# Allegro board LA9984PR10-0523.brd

Outline 237.4 x 193.1 mm; copper layers: TOP, GND1, IN1, VCC, IN2, IN3, GND2, BOTTOM. Coordinates in mm from the lower left corner of the outline.
Outline path: 0,122.4 24.21,122.4 arc(27.29,124.08) 29.86,121.7 arc(30.21,121.13) 30.84,120.9 37,120.9 arc(37.71,121.19) 38,121.9 38,122.4 48,122.4 arc(64.27,126.17) 77.23,136.71 arc(77.58,137) 78.02,137.1 78.62,137.1 arc(79.08,137.21) 79.44,137.53 arc(81.38,140.63) 83.02,143.9 arc(83.09,144.51) 82.79,145.04 arc(82.5,145.54) 82.54,146.13 arc(84.38,152.65) 85,159.4 85,161.8 88.93,161.8 88.93,155.52 arc(89.37,154.46) 90.43,154.02 117.73,154.02 arc(118.79,154.46) 119.23,155.52 119.23,161.8 123.5,161.8 arc(124.21,162.09) 124.5,162.8 124.5,192.1 148.32,192.1 arc(149.03,192.39) 149.32,193.1 174.82,193.1 arc(175.11,192.39) 175.82,192.1 198.4,192.1 198.4,184.1 arc(198.69,183.39) 199.4,183.1 210.2,183.1 210.2,182.6 arc(210.49,181.89) 211.2,181.6 233.2,181.6 arc(233.91,181.89) 234.2,182.6 234.2,183.1 237.4,183.1 237.4,174.1 234.9,174.1 234.9,91.45 231.4,91.45 arc(230.69,91.16) 230.4,90.45 230.4,0 165.4,0 165.4,9.48 arc(165.11,10.19) 164.4,10.48 89.4,10.48 89.4,13.48 arc(89.11,14.19) 88.4,14.48 76.6,14.48 76.6,16.98 arc(76.45,17.33) 76.1,17.48 72.1,17.48 arc(71.75,17.33) 71.6,16.98 71.6,14.48 62.4,14.48 arc(61.69,14.19) 61.4,13.48 61.4,9.65 18.8,9.65 arc(18.09,9.36) 17.8,8.65 17.8,6.5 0,6.5 0,10.84 12.33,10.84 12.33,18.69 0,18.69 0,23.6 7.12,23.6 arc(7.62,24.1) 7.12,24.6 7.12,36.21 arc(7.62,36.71) 7.12,37.21 0,37.21 0,41.25 10.07,41.25 arc(10.57,41.75) 10.07,42.25 10.07,53.75 arc(10.57,54.25) 10.07,54.75 0,54.75 0,58.85 10.07,58.85 arc(10.57,59.35) 10.07,59.85 10.07,71.35 arc(10.57,71.85) 10.07,72.35 0,72.35 0,76.66 12.5,76.66 arc(13,77.16) 12.5,77.66 12.5,91.94 arc(13,92.44) 12.5,92.94 0,92.94 0,97.9 6.55,97.9 arc(7.05,98.4) 6.55,98.9 6.55,112.4 arc(7.05,112.9) 6.55,113.4 0,113.4 0,122.4

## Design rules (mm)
net group CLK_: nets CLK_CPU_ITP CLK_CPU_ITP#
net group CSI: nets CSIN CSIP
net group DIFFPAIR2: nets I2C1_SCL_TCH_PAD I2C1_SDA_TCH_PAD
net group DIFFPAIR3: nets CSCL CSDA
net group DIFFPAIR5: nets EC_SMB_CK2 EC_SMB_DA2
net group DIFFPAIR6: nets CPU_DPB_CTRLCLK_R CPU_DPB_CTRLDAT_R
net group DIFFPAIR11: nets EDP_N1 EDP_P1
net group DIFFPAIR12: nets CPU_EDP_AUX#_C CPU_EDP_AUX_C
net group EDID_CLK: nets EDID_CLK EDID_DATA
net group MIIC_SCL: nets MIIC_SCL MIIC_SDA
net group PCIE_PRX_LANTX_P3_C: nets PCIE_PRX_LANTX_N3_C PCIE_PRX_LANTX_P3_C
net group PECI-SINGLE: nets PECI_EC PECI_KB9012
net group SENSE: nets VCCSENSE VSSSENSE
net group SMB-15: nets SML1_SMBCLK SML1_SMBDATA
net group VCIN0_PH: nets ECAGND VCIN0_PH
net group WCKA0_0: nets WCKA0_0 WCKA0B_0
net group WCKA0_1: nets WCKA0_1 WCKA0B_1
net group WCKA1_0: nets WCKA1_0 WCKA1B_0
net group WCKA1_1: nets WCKA1_1 WCKA1B_1
net group WCKB0_0: nets WCKB0_0 WCKB0B_0
net group WCKB0_1: nets WCKB0_1 WCKB0B_1
net group WCKB1_0: nets WCKB1_0 WCKB1B_0
net group WCKB1_1: nets WCKB1_1 WCKB1B_1
net group 12: nets PCH_OPI_COMP PCH_PCIE_RCOMP SATA_IREF
net group ASYNC: nets DDR3_DRAMRST# DDR3_DRAMRST#_CPU H_PROCHOT# H_PROCHOT#_R H_VCCST_PWRGD_XDP XDP_OBS0_R XDP_OBS1_R
net group AUDIO: nets PCH_AZ_BITCLK PCH_AZ_CODEC_BITCLK PCH_AZ_CODEC_RST# PCH_AZ_CODEC_SDIN0 PCH_AZ_CODEC_SDOUT PCH_AZ_CODEC_SYNC PCH_AZ_RST# PCH_AZ_SDOUT PCH_AZ_SYNC
net group CLK: nets SUSCLK
net group CLK-SINGLE: nets CLK_PCI_LPC
net group CR_LOW: nets DSWODVREN INTRUDER# PCH_DPWROK PCH_INTVRMEN PCH_RSMRST#_R SYS_PWROK SYS_PWROK_R SYS_RESET#
net group DDRA-ADD: nets DDR_A_BS0 DDR_A_BS1 DDR_A_BS2 DDR_A_CAS# DDR_A_MA0 DDR_A_MA1 DDR_A_MA2 DDR_A_MA3 DDR_A_MA4 DDR_A_MA5 DDR_A_MA6 DDR_A_MA7 DDR_A_MA8 DDR_A_MA9 DDR_A_MA10 DDR_A_MA11 DDR_A_MA12 DDR_A_MA13 DDR_A_MA14 DDR_A_MA15 DDR_A_RAS# DDR_A_WE#
net group DDRA-CTL: nets DDR_CKE0_DIMMA DDR_CKE1_DIMMA DDR_CS0_DIMMA# DDR_CS1_DIMMA# M_ODT0 M_ODT1
net group DDRA-D0: nets DDR_A_D0 DDR_A_D1 DDR_A_D2 DDR_A_D3 DDR_A_D4 DDR_A_D5 DDR_A_D6 DDR_A_D7
net group DDRA-D1: nets DDR_A_D8 DDR_A_D9 DDR_A_D10 DDR_A_D11 DDR_A_D12 DDR_A_D13 DDR_A_D14 DDR_A_D15 DDR_A_DQS1 DDR_A_DQS#1
net group DDRA-D2: nets DDR_A_D16 DDR_A_D17 DDR_A_D18 DDR_A_D19 DDR_A_D20 DDR_A_D21 DDR_A_D22 DDR_A_D23
net group DDRA-D3: nets DDR_A_D24 DDR_A_D25 DDR_A_D26 DDR_A_D27 DDR_A_D28 DDR_A_D29 DDR_A_D30 DDR_A_D31
net group DDRA-D4: nets DDR_A_D32 DDR_A_D33 DDR_A_D34 DDR_A_D35 DDR_A_D36 DDR_A_D37 DDR_A_D38 DDR_A_D39
net group DDRA-D5: nets DDR_A_D40 DDR_A_D41 DDR_A_D42 DDR_A_D43 DDR_A_D44 DDR_A_D45 DDR_A_D46 DDR_A_D47
net group DDRA-D6: nets DDR_A_D48 DDR_A_D49 DDR_A_D50 DDR_A_D51 DDR_A_D52 DDR_A_D53 DDR_A_D54 DDR_A_D55
net group DDRA-D7: nets DDR_A_D56 DDR_A_D57 DDR_A_D58 DDR_A_D59 DDR_A_D60 DDR_A_D61 DDR_A_D62 DDR_A_D63
net group DDRB-ADD: nets DDR_B_BS0 DDR_B_BS1 DDR_B_BS2 DDR_B_CAS# DDR_B_MA0 DDR_B_MA1 DDR_B_MA2 DDR_B_MA3 DDR_B_MA4 DDR_B_MA5 DDR_B_MA6 DDR_B_MA7 DDR_B_MA8 DDR_B_MA9 DDR_B_MA10 DDR_B_MA11 DDR_B_MA12 DDR_B_MA13 DDR_B_MA14 DDR_B_MA15 DDR_B_RAS# DDR_B_WE#
net group DDRB-CTL: nets DDR_CKE2_DIMMB DDR_CKE3_DIMMB DDR_CS2_DIMMB# DDR_CS3_DIMMB# M_ODT2 M_ODT3
net group DDRB-D0: nets DDR_B_D0 DDR_B_D1 DDR_B_D2 DDR_B_D3 DDR_B_D4 DDR_B_D5 DDR_B_D6 DDR_B_D7
net group DDRB-D1: nets DDR_B_D8 DDR_B_D9 DDR_B_D10 DDR_B_D11 DDR_B_D12 DDR_B_D13 DDR_B_D14 DDR_B_D15
net group DDRB-D2: nets DDR_B_D16 DDR_B_D17 DDR_B_D18 DDR_B_D19 DDR_B_D20 DDR_B_D21 DDR_B_D22 DDR_B_D23
net group DDRB-D3: nets DDR_B_D24 DDR_B_D25 DDR_B_D26 DDR_B_D27 DDR_B_D28 DDR_B_D29 DDR_B_D30 DDR_B_D31
net group DDRB-D4: nets DDR_B_D32 DDR_B_D33 DDR_B_D34 DDR_B_D35 DDR_B_D36 DDR_B_D37 DDR_B_D38 DDR_B_D39
net group DDRB-D5: nets DDR_B_D40 DDR_B_D41 DDR_B_D42 DDR_B_D43 DDR_B_D44 DDR_B_D45 DDR_B_D46 DDR_B_D47
net group DDRB-D6: nets DDR_B_D48 DDR_B_D49 DDR_B_D50 DDR_B_D51 DDR_B_D52 DDR_B_D53 DDR_B_D54 DDR_B_D55
net group DDRB-D7: nets DDR_B_D56 DDR_B_D57 DDR_B_D58 DDR_B_D59 DDR_B_D60 DDR_B_D61 DDR_B_D62 DDR_B_D63
net group DP: nets CPU_DPB_AUX CPU_DPB_AUX# CPU_DPC_AUX CPU_DPC_AUX#
net group EDP: nets CPU_EDP_N0_C CPU_EDP_N1_C CPU_EDP_P0_C CPU_EDP_P1_C
net group HDA: nets AUD_HP_OUT_L_CN AUD_HP_OUT_R_CN HPOUT-L HPOUT-R MIC_IN MIC_IN_R RING2 RING2_R
net group HDMI: nets TMDS_L_TX0N TMDS_L_TX0P TMDS_L_TX1N TMDS_L_TX1P TMDS_L_TX2N TMDS_L_TX2P TMDS_L_TXCN TMDS_L_TXCP TMDS_TX0N TMDS_TX0P TMDS_TX1N TMDS_TX1P TMDS_TX2N TMDS_TX2P TMDS_TXCN TMDS_TXCP
net group KB: nets KSI0 KSI1 KSI2 KSI3 KSI4 KSI5 KSI6 KSI7 KSO0 KSO1 KSO2 KSO3 KSO4 KSO5 KSO6 KSO7 KSO8 KSO9 KSO10 KSO11 KSO12 KSO13 KSO14 KSO15 KSO16
net group LPC: nets LPC_LAD0 LPC_LAD1 LPC_LAD2 LPC_LAD3 LPC_LFRAME#
net group LVDS: nets EDP_AUX EDP_AUX# EDP_N0 EDP_P0 LVDS_A0+ LVDS_A0- LVDS_A1+ LVDS_A1- LVDS_A2+ LVDS_A2- LVDS_ACLK+ LVDS_ACLK- LVDS_B0+ LVDS_B0- LVDS_B1+ LVDS_B1- LVDS_B2+ LVDS_B2- LVDS_BCLK+ LVDS_BCLK-
net group PCIE: nets PCIE_PRX_LANTX_N3 PCIE_PRX_LANTX_P3 PCIE_PTX_LANRX_N3 PCIE_PTX_LANRX_P3 PCIE_PTX_WLANRX_N4_C PCIE_PTX_WLANRX_P4_C
net group PEG: nets PEG_CTX_GRX_N0 PEG_CTX_GRX_N1 PEG_CTX_GRX_N2 PEG_CTX_GRX_N3 PEG_CTX_GRX_P0 PEG_CTX_GRX_P1 PEG_CTX_GRX_P2 PEG_CTX_GRX_P3
net group POWER: nets +0.675VS +0.675VSP +1.05VS +1.5VS +1.5VSP +1.5VSP_ON +1.35V +1.35VP +1.35VS_VGA +3V_WLAN +3VALW_PCH +3VALWP +3VLP +3VS +3VS_CAM +3VS_RT +5V_HDD +5V_PVDD +5V_USB_PWR1 +5V_USB_PWR2 +5V_USB_PWR3 +5V_USB_PWR4 +5VA +5VALWP +5VS_ODD +AVCC33 +DIMM1_VREF_DQ +DIMM2_VREF_DQ +DVCC33 +EC_VCCA +FAN_POWER +INV_PWR_SRC +LAN_IO +LAN_VDD +LCDVDD +MIC2-VREFO +PCH_VCCDSW +PCH_VCCDSW_R +RTCBATT +RTCVCC +SM_VREF_CA +SM_VREF_CA_DIMM +SM_VREF_DQ0 +SM_VREF_DQ0_DIMM1 +SM_VREF_DQ1 +SM_VREF_DQ1_DIMM2 +SW_LX +SWR_V12 +V18R +VCC_3IN1 +VCC_PWR_SRC +VCCIO_OUT +VCCIOA_OUT +VCHGR +VDISPLAY_VCC +VGA_CORE
net group RCOMP: nets SM_RCOMP0 SM_RCOMP1 SM_RCOMP2
net group RTC: nets PCH_RTCRST# PCH_RTCX1 PCH_RTCX2 SRTCRST#
net group SATA: nets SATA_PRX_DTX_N0 SATA_PRX_DTX_N0_C SATA_PRX_DTX_N1 SATA_PRX_DTX_P0 SATA_PRX_DTX_P0_C SATA_PRX_DTX_P1 SATA_PTX_DRX_N0 SATA_PTX_DRX_N1 SATA_PTX_DRX_N1_C SATA_PTX_DRX_P0 SATA_PTX_DRX_P1 SATA_PTX_DRX_P1_C
net group SMB_10: nets DDR_XDP_SMBCLK_R1 DDR_XDP_SMBDAT_R1 SML0CLK SML0DATA
net group SPI: nets PCH_SPI_CLK PCH_SPI_CLK_R PCH_SPI_CS0# PCH_SPI_HOLD1# PCH_SPI_HOLD# PCH_SPI_MISO PCH_SPI_MISO_1 PCH_SPI_MOSI PCH_SPI_MOSI_1 PCH_SPI_WP1# PCH_SPI_WP#
net group SPK: nets INT-SPK-L+ INT-SPK-L- INT-SPK-R+ INT-SPK-R-
net group SVID: nets H_CPU_SVIDALRT# H_CPU_SVIDCLK H_CPU_SVIDDATA VR_SVID_ALRT# VR_SVID_CLK VR_SVID_DAT
net group THERMTRIP-SINGLE: nets H_THERMTRIP#
net group USB20: nets USB20_CAM_N7_R USB20_CAM_P7_R USB20_CR_N6_R USB20_CR_P6_R USB20_JUSB3_N2 USB20_JUSB3_N2_R USB20_JUSB3_P2 USB20_JUSB3_P2_R USB20_USBDB_N3_R USB20_USBDB_P3_R
net group USB30: nets USB3RN1_JUSB2 USB3RN1_JUSB2_R USB3RN2_JUSB1 USB3RN2_JUSB1_R USB3RP1_JUSB2 USB3RP1_JUSB2_R USB3RP2_JUSB1 USB3RP2_JUSB1_R USB3TN1_JUSB2_C USB3TN1_JUSB2_R USB3TN2_JUSB1_C USB3TN2_JUSB1_R USB3TP1_JUSB2_C USB3TP1_JUSB2_R USB3TP2_JUSB1_C USB3TP2_JUSB1_R
net group VRAMA1-D0: nets DDBIA1_0 DQA1_0 DQA1_1 DQA1_2 DQA1_3 DQA1_4 DQA1_5 DQA1_6 DQA1_7 EDCA1_0
net group VRAMA1-D1: nets DDBIA1_1 DQA1_8 DQA1_9 DQA1_10 DQA1_11 DQA1_12 DQA1_13 DQA1_14 DQA1_15 EDCA1_1
net group VRAMA1-D2: nets DDBIA1_2 DQA1_16 DQA1_17 DQA1_18 DQA1_19 DQA1_20 DQA1_21 DQA1_22 DQA1_23 EDCA1_2
net group VRAMA1-D3: nets DDBIA1_3 DQA1_24 DQA1_25 DQA1_26 DQA1_27 DQA1_28 DQA1_29 DQA1_30 DQA1_31 EDCA1_3
net group VRAMA-ADD: nets ADBIA0 ADBIA1 CASA0# CASA1# CKEA0 CKEA1 CSA0#_0 CSA1#_0 MAA0_0 MAA0_1 MAA0_2 MAA0_3 MAA0_4 MAA0_5 MAA0_6 MAA0_7 MAA0_8 MAA1_0 MAA1_1 MAA1_2 MAA1_3 MAA1_4 MAA1_5 MAA1_6 MAA1_7 MAA1_8 RASA0# RASA1# WEA0# WEA1#
net group VRAMA-D0: nets DDBIA0_0 DQA0_0 DQA0_1 DQA0_2 DQA0_3 DQA0_4 DQA0_5 DQA0_6 DQA0_7 EDCA0_0
net group VRAMA-D1: nets DDBIA0_1 DQA0_8 DQA0_9 DQA0_10 DQA0_11 DQA0_12 DQA0_13 DQA0_14 DQA0_15 EDCA0_1
net group VRAMA-D2: nets DDBIA0_2 DQA0_16 DQA0_17 DQA0_18 DQA0_19 DQA0_20 DQA0_21 DQA0_22 DQA0_23 EDCA0_2
net group VRAMA-D3: nets DDBIA0_3 DQA0_24 DQA0_25 DQA0_26 DQA0_27 DQA0_28 DQA0_29 DQA0_30 DQA0_31 EDCA0_3
net group VRAMB0-D0: nets DDBIB0_0 DQB0_0 DQB0_1 DQB0_2 DQB0_3 DQB0_4 DQB0_5 DQB0_6 DQB0_7 EDCB0_0
net group VRAMB0-D1: nets DDBIB0_1 DQB0_8 DQB0_9 DQB0_10 DQB0_11 DQB0_12 DQB0_13 DQB0_14 DQB0_15 EDCB0_1
net group VRAMB0-D2: nets DDBIB0_2 DQB0_16 DQB0_17 DQB0_18 DQB0_19 DQB0_20 DQB0_21 DQB0_22 DQB0_23 EDCB0_2
net group VRAMB0-D3: nets DDBIB0_3 DQB0_24 DQB0_25 DQB0_26 DQB0_27 DQB0_28 DQB0_29 DQB0_30 DQB0_31 EDCB0_3
net group VRAMB1-D0: nets DDBIB1_0 DQB1_0 DQB1_1 DQB1_2 DQB1_3 DQB1_4 DQB1_5 DQB1_6 DQB1_7 EDCB1_0
net group VRAMB1-D1: nets DDBIB1_1 DQB1_8 DQB1_9 DQB1_10 DQB1_11 DQB1_12 DQB1_13 DQB1_14 DQB1_15 EDCB1_1
net group VRAMB1-D2: nets DDBIB1_2 DQB1_16 DQB1_17 DQB1_18 DQB1_19 DQB1_20 DQB1_21 DQB1_22 DQB1_23 EDCB1_2
net group VRAMB1-D3: nets DDBIB1_3 DQB1_24 DQB1_25 DQB1_26 DQB1_27 DQB1_28 DQB1_29 DQB1_30 DQB1_31 EDCB1_3
net group VRAMB-ADD: nets ADBIB0 ADBIB1 CASB0# CASB1# CKEB0 CKEB1 CSB0#_0 CSB1#_0 DRAM_RST# DRAM_RST#_R MAB0_0 MAB0_1 MAB0_2 MAB0_3 MAB0_4 MAB0_5 MAB0_6 MAB0_7 MAB0_8 MAB1_0 MAB1_1 MAB1_2 MAB1_3 MAB1_4 MAB1_5 MAB1_6 MAB1_7 MAB1_8 RASB0# RASB1# WEB0# WEB1#
nets with their own width: min track width 0.254; nets +1.8VSP +3VALW +VGA_PCIEP CLK_BIASREF
nets with their own width: min track width 0.508; nets +1.2VSP_B+ +1.05V_PGOOD +1.05VS_APLLOPI +1.05VS_ASATA3PLL +1.05VS_AUSB3PLL +1.05VS_AXCK_DCB +1.05VS_AXCK_LCPLL +1.05VSP +1.8VGS +1.8VS +1.8VSP_ON +1.35V_MEM_GFX +1.35VGPUP +3VALW_PCH_GATE +3VGS +5VALW +5VS +AVDD +BIF_VDDC +CHGRTC +CPU_CORE +DPAB_VDD10 +DPAB_VDD18 +DPCD_VDD10 +DPCD_VDD18 +DPEF_VDD10 +DPEF_VDD18 +DPLL_PVDD +DPLL_VDDC +LCDVDD_CONN +MPV18 +PCIE_PVDD +PCIE_VDDR +SPV10 +SPV18 +TSVDD +VCCIO_OUT_R +VCCRTCEXT +VDD1DI +VDD_MEM15_REFDA +VDD_MEM15_REFDB +VDD_MEM15_REFSA +VDD_MEM15_REFSB +VDDC_CT +VDDCI +VDDCIP +VDDR4 +VREFG_GPU EDP_COMP GND GNDA

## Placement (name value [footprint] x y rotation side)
C35  -  [C_0402]  107.79 98.93 270 bottom
C36  -  [C_0402]  105.63 98.93 270 bottom
C37  -  [C_0402]  103.47 98.93 270 bottom
C38  -  [C_0402]  101.31 98.93 270 bottom
C39  -  [C_0603]  108.87 99.18 270 bottom
C40  -  [C_0603]  99.44 114.61 270 top
C41  -  [C_0603]  106.71 99.11 270 bottom
C42  -  [C_0603]  104.55 99.11 270 bottom
C43  -  [C_0603]  103.57 114.34 270 top
C44  -  [C_0603]  130.39 138.86 270 top
C45  -  [C_0603]  102.39 99.11 270 bottom
C50  -  [C_0402]  123.22 120.33 270 top
C51  -  [C_0402]  149.5 107.75 0 top
C52  -  [C_0402]  124.68 113.96 90 top
C53  -  [C_0402]  124.55 121.69 180 top
C54  -  [C_0402]  134.08 99.32 270 bottom
C55  -  [C_0402]  134.97 99.32 270 bottom
C56  -  [C_0402]  135.86 99.32 270 bottom
C57  -  [C_0402]  130.34 123.05 180 top
C58  -  [C_0402]  120.48 133.47 0 bottom
C59  -  [C_1206]  119.66 136.58 0 bottom
C60  -  [C_0603]  131.03 124.64 90 top
C61  -  [C_0402]  122.79 121.72 180 top
C62  -  [C_0402]  129.95 125.07 90 top
C63  -  [C_0402]  125.31 132.63 90 bottom
C64  -  [C_0402]  118.33 98.43 270 top
C65  -  [C_1206]  125.44 136.58 0 bottom
C66  -  [C_0603]  119.73 96.45 180 top
C67  -  [C_0402]  119.99 113.08 180 top
C68  -  [C_0402]  123.85 116.65 270 top
C69  -  [C_0402]  118.9 116.52 270 top
C70  -  [C_1206]  125.3 138.55 0 bottom
C71  -  [C_0402]  121.69 120.4 270 top
C72  -  [C_0603]  100.23 99.11 270 bottom
C73  -  [C_0402]  122.72 118.04 180 top
C74  -  [C_0603]  99.03 99.11 270 bottom
C75  -  [C_0402]  117.52 112.98 90 top
C76  -  [C_0402]  120.29 114.67 0 top
C77  -  [C_0402]  121.05 111.51 0 top
C78  -  [C_0603]  122.9 115.75 180 top
C79  -  [C_0402]  92.04 130.76 90 bottom
C80  -  [C_0402]  89.41 119.7 0 top
C81  -  [C_0402]  124.36 111.76 270 top
C82  -  [C_0603]  122.9 116.96 180 top
C83  -  [C_0402]  119.6 121.98 270 top
C84  -  [C_1206]  121.3 139.04 0 bottom
C85  -  [C_0402]  119.61 133.47 180 bottom
C86  -  [C_1206]  118.27 136.59 180 bottom
C87  -  [C_0402]  120.3 115.55 90 top
C88  -  [C_0402]  117.5 119.38 270 top
C2305  -  [C_0603]  190.4 21.58 180 top
C2306  -  [C_0603]  190.4 20.37 180 top
C2307  -  [C_0805]  199.46 20.7 0 top
C2308  -  [C_0603]  199.42 22.23 0 top
C2309  -  [C_0603]  187.97 19.94 180 top
C2310  -  [C_0805]  142.31 29.52 0 top
C2311  -  [C_0603]  142.9 24.13 0 top
C2312  -  [C_0603]  142.21 31.04 0 top
C2313  -  [C_0603]  142.9 22.93 0 top
C2314  -  [C_0603]  141.06 27.56 0 bottom
C2316  -  [C_0603]  190.97 17.9 180 top
C2318  -  [C_0603]  190.97 19.1 180 top
C2322  -  [C_0603]  187.97 18.74 180 top
C2323  -  [C_0603]  199.36 17.91 0 top
C2324  -  [C_0603]  199.36 19.12 0 top
C2326  -  [C_0402]  142.55 116.98 180 bottom
C2327  -  [C_0402]  168.06 92.91 180 bottom
C5212  -  [C_0402]  83.2 119.81 0 bottom
CA1  -  [C_0603]  27.4 25.97 0 bottom
CA2  -  [C_0603]  27.97 27.36 90 bottom
CA21  -  [C_0402]  46.69 24.37 0 top
CA22  -  [C_0402]  46.69 23.42 0 top
CA23  -  [C_0603]  32.48 26.28 0 top
CA24  -  [C_0402]  34.71 22.15 180 top
CA25  -  [C_0402]  33.35 23.17 0 top
CA29  -  [C_0402]  63.59 36.81 90 top
CA30  -  [C_0402]  63.59 35.94 270 top
CA31  -  [C_0402]  64.54 33.76 90 top
CA32  -  [C_0402]  64.54 32.89 270 top
CA33  -  [C_0402]  28.25 20.51 180 top
CA38  -  [C_0402]  19.64 25.33 90 top
CA39  -  [C_0402]  29.18 20.51 0 top
CA40  -  [C_0402]  19.64 24.46 270 top
CA51  -  [C_0402]  34.26 28.49 90 top
CA53  -  [C_0603]  42.45 18.35 270 top
CA54  -  [C_0402]  42.64 19.29 90 top
CA55  -  [C_0603]  43.59 18.15 0 top
CA56  -  [C_0402]  43.51 19.23 0 top
CA57  -  [C_0603]  44.35 21.07 0 top
CA58  -  [C_0402]  44.34 22.15 0 top
CA59  -  [C_0603]  44.48 27.61 0 top
CA60  -  [C_0402]  44.4 26.53 0 top
CA61  -  [C_0603]  37.18 17.15 180 top
CA62  -  [C_0603]  32.48 27.48 0 top
CA63  -  [C_0603]  35.78 18.53 90 top
CA64  -  [C_0603]  48.03 25.45 180 top
CA65  -  [C_0402]  44.4 28.69 0 top
CA67  -  [C_0603]  36.99 29.77 90 top
CA68  -  [C_0603]  38.19 29.77 90 top
CA69  -  [C_0402]  45.32 29.58 180 top
CA71  -  [C_0603]  33.18 28.56 90 top
CA74  -  [C_0603]  39.65 30.02 90 top
CC1  -  [C_0402]  146 101.14 0 bottom
CC2  -  [C_0402]  148.7 101.14 180 bottom
CC3  -  [C_0402]  129.45 96.77 90 top
CC4  -  [C_0402]  132.56 96.77 90 top
CC5  -  [C_0402]  127.21 97.27 0 bottom
CC6  -  [C_0402]  118.92 136.47 180 top
CC7  -  [C_0402]  114.45 136.47 0 top
CC8  -  [C_0402]  97.05 97.54 0 bottom
CC9  -  [C_0402]  94.41 97.54 180 bottom
CC10  -  [C_0402]  96.19 97.54 180 bottom
CC11  -  [C_0402]  149.5 105.4 0 top
CC13  -  [C_0402]  70.27 110.35 90 bottom
CC14  -  [C_0402]  62.7 103.69 90 bottom
CC15  -  [C_0402]  62.65 92.71 180 top
CC16  -  [C_0402]  61.89 90.7 270 bottom
CC17  -  [C_0402]  60.94 103.69 90 bottom
CC18  -  [C_0402]  158.88 119.95 0 bottom
CC19  -  [C_0402]  158.88 119.06 0 bottom
CC20  -  [C_0402]  160.66 121.47 0 bottom
CC21  -  [C_0402]  160.66 120.58 0 bottom
CC22  -  [C_0402]  158.88 122.74 0 bottom
CC23  -  [C_0402]  158.88 121.85 0 bottom
CC24  -  [C_0402]  160.66 124.52 0 bottom
CC25  -  [C_0402]  160.66 123.63 0 bottom
CC26  -  [C_0603]  136.93 99.3 270 bottom
CC27  -  [C_0402]  86.53 130.86 0 bottom
CC28  -  [C_0402]  78.98 124.51 90 bottom
CC29  -  [C_0402]  67.61 108.59 180 bottom
CC30  -  [C_0402]  62.2 106.95 270 bottom
CC31  -  [C_0402]  133.51 112.26 90 top
CC32  -  [C_0402]  39.91 102.02 90 bottom
CC33  -  [C_0402]  147.03 109.81 270 top
CC34  -  [C_0402]  135.3 113.73 180 top
CC35  -  [C_0402]  122.19 96.97 0 bottom
CC40  -  [C_0402]  39.02 102.02 90 bottom
CD1  -  [C_0402]  42.37 74.86 0 top
CD2  -  [C_0402]  42.37 75.74 0 top
CD3  -  [C_0402]  51.27 64.56 90 top
CD4  -  [C_0402]  73.88 64.49 90 top
CD5  -  [C_0402]  68.99 65.06 90 top
CD6  -  [C_0402]  66.7 65.41 270 top
CD7  -  [C_0402]  65.37 74.02 90 top
CD8  -  [C_0402]  69.94 72.68 90 top
CD9  -  [C_0402]  77.5 64.49 90 top
CD10  -  [C_0402]  77.18 72.68 90 top
CD11  -  [C_0402]  73.63 72.68 90 top
CD12  -  [C_0603]  75.72 64.57 90 top
CD13  -  [C_0603]  75.47 72.7 90 top
CD14  -  [C_0603]  78.96 72.7 90 top
CD15  -  [C_D3]  73.27 78.03 180 top
CD16  -  [C_0603]  67.91 64.57 90 top
CD17  -  [C_0603]  72.1 64.57 90 top
CD18  -  [C_0603]  79.34 64.57 90 top
CD19  -  [C_0603]  66.51 73.78 90 top
CD20  -  [C_0603]  71.78 72.7 90 top
CD21  -  [C_0402]  81.69 64.56 90 top
CD22  -  [C_0402]  82.58 64.56 90 top
CD23  -  [C_0402]  79.09 59.2 270 top
CD24  -  [C_0402]  105.26 72.76 180 top
CD25  -  [C_0402]  105.26 73.65 180 top
CD26  -  [C_0402]  105.01 64.95 180 top
CD27  -  [C_0402]  104.94 65.84 180 top
CD28  -  [C_0603]  105.29 66.92 180 top
CD29  -  [C_0603]  105.25 74.73 180 top
CD30  -  [C_0402]  102.57 72.75 90 top
CD31  -  [C_0402]  103.47 72.75 90 top
CD32  -  [C_0402]  120.41 75.43 0 top
CD33  -  [C_0402]  120.41 74.54 0 top
CD34  -  [C_0402]  129.31 64.56 90 top
CD35  -  [C_0402]  152.49 64.56 90 top
CD36  -  [C_0402]  148.87 64.56 90 top
CD37  -  [C_0402]  145.25 64.56 90 top
CD38  -  [C_0402]  156.05 64.49 90 top
CD39  -  [C_0402]  156.3 73.4 90 top
CD40  -  [C_0402]  153.51 73.4 90 top
CD41  -  [C_0402]  149.57 73.4 90 top
CD42  -  [C_0402]  144.62 73.4 90 top
CD43  -  [C_0603]  150.65 64.57 90 top
CD44  -  [C_0603]  147.03 64.57 90 top
CD45  -  [C_0603]  154.27 64.57 90 top
CD46  -  [C_0603]  146.14 73.47 90 top
CD47  -  [C_0603]  148.49 73.47 90 top
CD48  -  [C_0603]  151.98 73.47 90 top
CD49  -  [C_0603]  155.22 73.47 90 top
CD50  -  [C_0603]  157.89 64.57 90 top
CD51  -  [C_D3]  153.23 83.75 0 top
CD52  -  [C_0402]  160.3 64.56 90 top
CD53  -  [C_0402]  161.19 64.56 90 top
CD54  -  [C_0402]  183.62 74.28 180 top
CD55  -  [C_0402]  183.62 75.17 180 top
CD56  -  [C_0402]  183.56 64.57 180 top
CD57  -  [C_0402]  183.56 65.46 180 top
CD58  -  [C_0603]  183.83 66.54 180 top
CD59  -  [C_0603]  183.54 76.25 180 top
CD60  -  [C_0402]  180.94 74.27 90 top
CD61  -  [C_0402]  181.83 74.27 90 top
CD62  -  [C_0603]  101.44 72.74 90 top
CD63  -  [C_0402]  55.96 18.82 0 top
CD64  -  [C_0402]  83.86 59.31 180 top
CE1  -  [C_0402]  199.41 38.91 0 top
CE2  -  [C_0402]  191.54 35.75 270 top
CE5  -  [C_0402]  178.51 39.55 0 top
CE6  -  [C_0402]  185.49 34.94 90 top
CE7  -  [C_0402]  200.61 36.5 0 top
CE8  -  [C_0402]  196.31 55.79 90 top
CE9  -  [C_0402]  200.45 51.36 180 top
CE11  -  [C_0402]  199.47 41.84 0 top
CE12  -  [C_0402]  187.4 33.83 0 top
CE15  -  [C_0402]  178.08 57.32 90 top
CE16  -  [C_0805]  179.3 40.83 180 top
CE18  -  [C_0402]  178.58 46.85 0 top
CE19  -  [C_0402]  179.48 57.32 90 top
CE20  -  [C_0402]  195.55 32.81 90 top
CE22  -  [C_0603]  48.73 108.07 180 bottom
CE23  -  [C_0402]  48.81 106.99 180 bottom
CE24  -  [C_0402]  50.05 108.13 0 bottom
CE25  -  [C_0603]  44.73 104.32 270 bottom
CE26  -  [C_0402]  183.61 55.35 90 top
CE27  -  [C_0402]  184.62 35.85 270 top
CE28  -  [C_0402]  189.18 33.91 0 top
CE29  -  [C_0402]  193.96 35.75 270 top
CE30  -  [C_0402]  178.39 45.53 180 top
CE31  -  [C_0402]  196.83 35.82 270 top
CE32  -  [C_0402]  188.27 57.06 90 top
CE33  -  [C_0402]  181.19 34.99 0 top
CE34  -  [C_0402]  175.47 42.45 90 top
CE35  -  [C_0402]  174.41 40.74 0 top
CE36  -  [C_0402]  188.31 35.62 270 top
CE56  -  [C_0603]  42.95 104.65 0 top
CE57  -  [C_0603]  38.45 111.89 90 top
CE58  -  [C_0603]  33.61 98.38 0 top
CG1  -  [C_0402]  64.18 48.48 90 top
CG2  -  [C_0402]  63.41 42.36 270 top
CG3  -  [C_0402]  66.73 45.46 0 top
CG4  -  [C_0402]  60.35 46.92 180 top
CG5  -  [C_0805]  65.9 48.59 90 top
CG6  -  [C_0603]  62.14 48.52 90 top
CG7  -  [C_0402]  66.15 41.61 90 top
CG8  -  [C_0402]  60.29 42.47 0 top
CG9  -  [C_0402]  60.46 43.5 90 top
CG10  -  [C_0402]  62.53 42.36 270 top
CG11  -  [C_0402]  63.26 50.31 90 top
CI1  -  [C_MP6VLPS220MC4R2]  26.25 66.99 270 bottom
CI2  -  [C_0402]  19.21 65.98 270 bottom
CI3  -  [C_0402]  23.33 62.42 270 bottom
CI4  -  [C_0402]  24.22 62.42 270 bottom
CI6  -  [C_0805]  28.21 48.67 270 top
CI7  -  [C_0402]  29.54 47.77 270 top
CI8  -  [C_MP6VLPS220MC4R2]  26.25 52.83 270 bottom
CI9  -  [C_0402]  18.44 55.22 90 bottom
CI10  -  [C_0402]  23.7 49.89 0 bottom
CI11  -  [C_0402]  23.7 50.79 0 bottom
CI12  -  [C_0805]  28.83 61.6 0 top
CI13  -  [C_0402]  30.69 65.71 90 top
CI14  -  [C_0402]  29.61 64.65 0 top
CI15  -  [C_0402]  30.62 71.01 270 top
CI16  -  [C_0402]  21 36.2 180 top
CI17  -  [C_0402]  30.69 55.26 270 top
CI18  -  [C_0805]  28.83 59.88 0 top
CI19  -  [C_0402]  15.4 34.52 90 bottom
CI20  -  [C_MP6VLPS220MC4R2]  26.19 34.86 270 bottom
CI21  -  [C_0805]  28.83 63.31 0 top
CI22  -  [C_0402]  23 32.2 0 top
CI23  -  [C_0805]  22.04 33.53 0 top
CI24  -  [C_0402]  16.36 36.18 180 top
CI25  -  [C_0402]  213.4 37.53 180 bottom
CI26  -  [C_0402]  30.43 47.77 270 top
CI27  -  [C_0805]  22.7 35.03 90 top
CI30  -  [C_0402]  217.58 39.44 0 bottom
CI31  -  [C_0805]  216.81 40.77 0 bottom
CI32  -  [C_0402]  209.57 37.59 0 bottom
CI40  -  [C_0603]  20.29 66.54 270 bottom
CI43  -  [C_0603]  17.36 55.11 90 bottom
CI44  -  [C_0603]  14.32 34.34 90 bottom
CL15  -  [C_0402]  34.19 83.9 270 bottom
CL19  -  [C_0402]  42.95 86.11 270 bottom
CL20  -  [C_0402]  35.97 83.95 270 bottom
CL22  -  [C_0402]  34.2 91.3 180 bottom
CL26  -  [C_0402]  34.2 92.19 180 bottom
CL30  -  [C_0402]  42.07 91.82 270 bottom
CL31  -  [C_0402]  42.95 91.82 270 bottom
CL33  -  [C_1206]  19.21 81.78 270 top
CL34  -  [C_0402]  35.97 91.86 90 bottom
CL35  -  [C_0402]  35.08 91.86 90 bottom
CL36  -  [C_0402]  37.1 84.03 270 bottom
CL37  -  [C_0402]  38.57 83.1 90 bottom
CL38  -  [C_0603]  47.32 88.83 0 bottom
CL39  -  [C_0402]  43.78 84.13 180 bottom
CL41  -  [C_0402]  32.99 87.45 270 bottom
CM40  -  [C_0402]  93.31 148.19 0 top
CM43  -  [C_0603]  111.68 150.32 0 top
CM44  -  [C_0402]  108.33 149.73 90 top
CM45  -  [C_0603]  94.24 146.74 270 top
CM46  -  [C_0402]  115.87 149.7 90 top
CM47  -  [C_0402]  104.69 149.76 90 top
CM48  -  [C_0402]  110.73 149.74 90 top
CM49  -  [C_0402]  107.45 149.73 90 top
CMOS1  -  [SHORTPADS]  113.11 40.96 0 bottom
CR1  -  [C_0402]  177.96 20.77 270 top
CR2  -  [C_0603]  179.04 20.69 270 top
CR3  -  [C_0402]  180.11 19.85 90 top
CR4  -  [C_0402]  173.38 22.65 90 top
CR5  -  [C_0402]  181.78 22.85 180 top
CR6  -  [C_0402]  177.32 29.66 270 top
CR7  -  [C_0402]  182.26 30.6 0 top
CR8  -  [C_0603]  189.2 31.02 270 top
CR9  -  [C_0402]  179.49 28.78 0 top
CR10  -  [C_0402]  182.82 23.95 270 top
CR11  -  [C_0402]  175.16 28.74 90 top
CS5  -  [C_0402]  224.01 55.34 90 top
CS6  -  [C_0402]  223.12 55.34 90 top
CS7  -  [C_0805]  221.77 54.65 90 top
CS8  -  [C_0402]  224.7 103.89 180 bottom
CS9  -  [C_0402]  224.73 103.01 180 bottom
CS10  -  [C_0402]  223.18 115.5 180 bottom
CS11  -  [C_0402]  223.18 114.61 180 bottom
CS12  -  [C_0805]  223 113.21 180 bottom
CS13  -  [C_0402]  219.5 120.19 180 bottom
CS14  -  [C_0402]  224.77 109.16 180 bottom
CS15  -  [C_0402]  224.77 108.27 180 bottom
CS16  -  [C_0603]  223.07 124.75 0 bottom
CS17  -  [C_0402]  224.68 110.25 180 bottom
CS105  -  [C_0402]  224.39 30.02 180 top
CS106  -  [C_0402]  224.39 30.91 180 top
CS108  -  [C_0402]  224.39 32.69 180 top
CS109  -  [C_0402]  224.39 31.8 180 top
CV1  -  [C_0603]  196.62 158.55 90 top
CV3  -  [C_0603]  195.42 158.55 90 top
CV4  -  [C_0603]  218.53 124.39 0 top
CV5  -  [C_0603]  218.53 125.59 0 top
CV6  -  [C_0603]  218.02 104.13 270 top
CV7  -  [C_0603]  216.82 104.13 270 top
CV8  -  [C_0402]  164.43 158.22 90 top
CV9  -  [C_0402]  163.54 158.22 90 top
CV10  -  [C_0402]  194.85 158.15 90 bottom
CV11  -  [C_0402]  193.13 158.34 90 top
CV12  -  [C_0402]  219.03 133.97 0 top
CV13  -  [C_0402]  218.52 143.31 0 bottom
CV14  -  [C_0402]  165.89 158.22 90 bottom
CV15  -  [C_0402]  164.81 158.22 90 bottom
CV16  -  [C_0402]  163.92 158.22 90 bottom
CV17  -  [C_0402]  173.7 158.54 90 bottom
CV18  -  [C_0402]  219.48 145.1 270 bottom
CV19  -  [C_0402]  218.46 129.34 0 bottom
CV20  -  [C_0402]  218.46 127.56 0 bottom
CV21  -  [C_0402]  200.5 133.02 0 bottom
CV22  -  [C_0402]  201.41 134.8 180 bottom
CV23  -  [C_0402]  218.71 127.56 0 top
CV24  -  [C_0402]  219.62 129.34 180 top
CV25  -  [C_0402]  205.51 144.63 90 top
CV26  -  [C_0402]  203.74 145.54 270 top
CV27  -  [C_0402]  201.46 132.98 180 top
CV28  -  [C_0402]  200.55 130.35 0 top
CV29  -  [C_0402]  212.64 103.18 180 bottom
CV30  -  [C_0402]  211.73 101.4 0 bottom
CV31  -  [C_0402]  205.26 103.82 270 bottom
CV32  -  [C_0402]  203.48 102.91 90 bottom
CV33  -  [C_0402]  201.22 114.78 180 top
CV34  -  [C_0402]  200.31 116.56 0 top
CV35  -  [C_0402]  213.64 102.11 270 top
CV36  -  [C_0402]  211.86 101.19 90 top
CV37  -  [C_0402]  218.46 121.21 0 top
CV38  -  [C_0402]  218.46 119.43 0 top
CV39  -  [C_0402]  201.22 114.78 180 bottom
CV40  -  [C_0402]  200.31 116.56 0 bottom
CV41  -  [C_0603]  167.03 158.24 90 bottom
CV42  -  [C_0603]  162.78 158.17 90 bottom
CV43  -  [C_0402]  159.08 119.62 0 top
CV44  -  [C_0402]  159.08 118.73 0 top
CV45  -  [C_0402]  160.92 120.77 0 top
CV46  -  [C_0402]  160.92 119.88 0 top
CV47  -  [C_0402]  159.08 121.97 0 top
CV48  -  [C_0402]  159.08 121.08 0 top
CV49  -  [C_0402]  160.92 122.23 0 top
CV50  -  [C_0402]  160.92 123.12 0 top
CV59  -  [C_0402]  173.7 158.54 90 top
CV60  -  [C_0402]  172.81 158.54 90 top
CV61  -  [C_0402]  170.97 158.22 90 top
CV62  -  [C_0402]  188.69 158.28 90 top
CV63  -  [C_0402]  189.32 158.15 90 bottom
CV64  -  [C_0402]  186.91 158.28 90 top
CV65  -  [C_0402]  187.93 158.15 90 bottom
CV66  -  [C_0402]  185.96 158.28 90 top
CV67  -  [C_0402]  187.04 158.15 90 bottom
CV68  -  [C_0402]  185.07 158.28 90 top
CV69  -  [C_0402]  170.08 158.22 90 top
CV70  -  [C_0402]  169.07 158.22 90 top
CV71  -  [C_0402]  168.18 158.22 90 top
CV72  -  [C_0402]  166.78 158.22 90 top
CV73  -  [C_0402]  165.89 158.22 90 top
CV74  -  [C_0402]  186.15 158.15 90 bottom
CV75  -  [C_0402]  166.09 116.07 270 top
CV76  -  [C_0402]  165.2 116.07 270 top
CV77  -  [C_0603]  163.73 115.23 270 top
CV78  -  [C_0402]  165.2 117.85 270 top
CV79  -  [C_0402]  166.09 117.85 270 top
CV80  -  [C_0603]  163.73 117.65 270 top
CV81  -  [C_0402]  185.01 104.25 180 bottom
CV82  -  [C_0603]  161.7 107.36 90 bottom
CV83  -  [C_0402]  170.45 110.98 0 top
CV84  -  [C_0402]  170.45 111.87 0 top
CV85  -  [C_0402]  179.86 96.58 270 bottom
CV86  -  [C_0603]  161.7 106.34 270 bottom
CV87  -  [C_0402]  170.57 107.93 0 top
CV88  -  [C_0402]  170.57 108.82 0 top
CV89  -  [C_0402]  178.03 94.66 180 bottom
CV91  -  [C_0603]  158.52 109.58 180 bottom
CV92  -  [C_0402]  158.6 107.55 180 bottom
CV93  -  [C_0402]  158.6 108.5 180 bottom
CV94  -  [C_0402]  170.54 103.17 180 bottom
CV95  -  [C_0402]  171.4 103.17 0 bottom
CV97  -  [C_0805]  166.59 128.17 90 top
CV101  -  [C_0603]  182.21 95.74 90 bottom
CV102  -  [C_0603]  180.94 95.74 90 bottom
CV103  -  [C_0603]  188.18 96.82 270 bottom
CV108  -  [C_0402]  174.22 108.69 180 top
CV109  -  [C_0402]  174.6 111.17 180 top
CV110  -  [C_0603]  161.7 106.34 270 top
CV111  -  [C_0603]  182.27 102.22 180 bottom
CV112  -  [C_0402]  182.34 103.31 180 bottom
CV113  -  [C_0402]  182.34 104.2 180 bottom
CV114  -  [C_0402]  160.55 107.92 90 top
CV115  -  [C_0402]  159.6 107.92 90 top
CV116  -  [C_0603]  158.52 108 90 top
CV117  -  [C_0603]  185.95 102.29 0 bottom
CV118  -  [C_0402]  185.88 104.25 0 bottom
CV119  -  [C_0402]  185.88 103.36 0 bottom
CV120  -  [C_0603]  157.63 106.41 270 top
CV121  -  [C_0402]  159.61 106.44 270 top
CV122  -  [C_0402]  158.72 106.44 270 top
CV123  -  [C_0603]  158.65 103.23 270 top
CV124  -  [C_0402]  160.62 103.23 270 top
CV125  -  [C_0402]  159.73 103.23 270 top
CV126  -  [C_0402]  155.79 114.55 270 top
CV127  -  [C_0402]  156.68 114.55 270 top
CV128  -  [C_0402]  155.22 116.24 90 top
CV129  -  [C_0402]  156.17 116.24 90 top
CV130  -  [C_0402]  157.57 114.55 270 top
CV131  -  [C_0603]  154.65 115.11 270 top
CV132  -  [C_0402]  161.13 117.95 90 bottom
CV133  -  [C_0402]  162.02 117.95 90 bottom
CV134  -  [C_0603]  159.73 116.63 90 bottom
CV135  -  [C_B2]  160.34 159.44 0 top
CV136  -  [C_0603]  197.83 158.54 90 top
CV137  -  [C_0603]  203.55 146.8 90 bottom
CV138  -  [C_0603]  218.34 115.3 0 bottom
CV139  -  [C_0603]  218.53 123.18 0 top
CV140  -  [C_0603]  194.21 158.54 90 top
CV141  -  [C_0402]  191.35 158.34 90 top
CV142  -  [C_0402]  171.49 134.16 180 top
CV143  -  [C_0402]  170.54 131.3 180 top
CV144  -  [C_0402]  186.27 111.44 270 top
CV145  -  [C_0402]  190.45 158.31 90 top
CV146  -  [C_0402]  172.16 122.61 0 top
CV147  -  [C_0402]  172.37 125.72 0 top
CV148  -  [C_0402]  172.37 126.62 0 top
CV149  -  [C_0402]  171.73 129.54 270 top
CV150  -  [C_0402]  170.54 130.41 180 top
CV151  -  [C_0603]  170.65 129.47 270 top
CV152  -  [C_0402]  162.21 158.22 90 top
CV153  -  [C_0402]  171.49 135.05 180 top
CV154  -  [C_0402]  188.3 111.12 0 top
CV155  -  [C_0402]  187.51 115.61 90 top
CV156  -  [C_0402]  186.08 119.72 270 top
CV170  -  [C_0603]  171.03 98.74 270 bottom
CV171  -  [C_0402]  173.06 98.74 270 bottom
CV172  -  [C_0402]  172.18 98.74 270 bottom
CV173  -  [C_0402]  173.58 116.79 270 top
CV174  -  [C_0402]  172.68 116.79 270 top
CV187  -  [C_0603]  177.19 115.42 270 top
CV188  -  [C_0402]  176.19 115.49 180 top
CV189  -  [C_0402]  175.43 114.6 180 top
CV190  -  [C_0402]  175.28 116.83 0 top
CV193  -  [C_0402]  186.59 115.69 270 top
CV194  -  [C_0402]  185.95 117 90 top
CV195  -  [C_0402]  174.52 126.53 0 top
CV196  -  [C_0402]  174.52 125.64 0 top
CV197  -  [C_0603]  202.39 149.61 0 top
CV198  -  [C_0402]  202.89 148.46 0 top
CV199  -  [C_0402]  202.89 147.45 0 top
CV200  -  [C_0603]  190.78 97.84 0 bottom
CV201  -  [C_0402]  191.14 99.82 0 bottom
CV202  -  [C_0402]  191.14 98.93 0 bottom
CV203  -  [C_0402]  183.54 122.71 0 top
CV204  -  [C_0402]  184.25 124.84 90 top
CV205  -  [C_0402]  183.49 121.77 0 top
CV206  -  [C_0402]  183.48 127.94 90 top
CV207  -  [C_0402]  179.54 127.64 0 top
CV208  -  [C_0402]  183.51 123.6 0 top
CV209  -  [C_0402]  184.45 126.62 180 top
CV210  -  [C_0402]  179.57 128.52 0 top
CV211  -  [C_0402]  182.6 127.94 90 top
CV212  -  [C_0402]  181.33 127.56 90 top
CV213  -  [C_0603]  182.75 109.49 270 top
CV214  -  [C_0603]  181.54 109.49 270 top
CV215  -  [C_0603]  194.59 97.84 180 bottom
CV216  -  [C_0402]  194.28 98.93 180 bottom
CV217  -  [C_0402]  194.28 99.82 180 bottom
CV218  -  [C_0402]  194.35 96.31 180 top
CV219  -  [C_0402]  191.53 94.47 0 top
CV220  -  [C_0402]  161.11 130.86 0 bottom
CV221  -  [C_0402]  161.11 135.36 0 bottom
CV222  -  [C_0402]  209.07 101.06 90 top
CV223  -  [C_0402]  196.2 105.28 90 bottom
CV224  -  [C_0402]  196.18 107.96 270 bottom
CV280  -  [C_0402]  218.52 140.96 0 bottom
CV281  -  [C_0402]  218.52 140.07 0 bottom
CV283  -  [C_0402]  218.52 138.61 0 bottom
CV284  -  [C_0402]  218.52 137.72 0 bottom
CV285  -  [C_0402]  218.52 136.45 0 bottom
CV286  -  [C_0402]  218.52 135.56 0 bottom
CV287  -  [C_0402]  218.52 133.78 0 bottom
CV288  -  [C_0402]  218.52 132.89 0 bottom
CV290  -  [C_0402]  218.52 132.01 0 bottom
CV291  -  [C_0402]  219.03 133.08 0 top
CV292  -  [C_0402]  219.03 134.86 0 top
CV293  -  [C_0402]  219.03 131.31 0 top
CV294  -  [C_0402]  219.03 130.42 0 top
CV295  -  [C_0402]  218.46 125.76 0 bottom
CV296  -  [C_0402]  218.46 124.87 0 bottom
CV297  -  [C_0402]  218.52 131.12 0 bottom
CV298  -  [C_0402]  218.33 115.88 0 top
CV299  -  [C_0402]  218.33 116.77 0 top
CV301  -  [C_0402]  218.33 111.3 0 bottom
CV302  -  [C_0402]  218.33 112.19 0 bottom
CV303  -  [C_0402]  218.39 114.16 0 bottom
CV304  -  [C_0402]  218.33 106.61 0 bottom
CV305  -  [C_0402]  218.71 107.62 0 top
CV306  -  [C_0402]  218.77 109.84 0 top
CV307  -  [C_0402]  218.77 112.19 0 top
CV308  -  [C_0402]  218.33 113.59 0 top
CV310  -  [C_0402]  218.39 117.65 0 top
CV311  -  [C_0402]  218.39 118.54 0 top
CV312  -  [C_0402]  218.39 113.27 0 bottom
CV313  -  [C_0402]  218.33 109.84 0 bottom
CV315  -  [C_0402]  218.33 108.95 0 bottom
CV316  -  [C_0402]  218.33 107.49 0 bottom
CV318  -  [C_0402]  218.71 106.73 0 top
CV319  -  [C_0402]  218.77 111.3 0 top
CV322  -  [C_0603]  183.99 119.89 270 top
CV323  -  [C_0603]  180.32 109.47 270 top
CV324  -  [C_0603]  177.77 127.43 90 top
CV325  -  [C_0402]  180.21 113.47 180 top
CV326  -  [C_0402]  161.82 111.69 270 bottom
CV327  -  [C_D2]  161.79 131.81 180 top
CV328  -  [C_0402]  170.78 140.2 90 top
CV329  -  [C_0402]  167.29 100.08 90 top
CV330  -  [C_0402]  158.13 150.55 0 top
CV331  -  [C_0402]  160.81 112.52 270 top
CV332  -  [C_0402]  180.62 158.28 90 top
CV333  -  [C_0402]  159.41 113.63 90 top
CV335  -  [C_0402]  155.92 112.2 270 top
CV349  -  [C_0402]  188.24 141.05 270 top
CV350  -  [C_0402]  190.02 140.13 90 top
CV351  -  [C_0402]  181.51 158.15 90 bottom
CV352  -  [C_0402]  183.29 159.07 270 bottom
CV353  -  [C_0402]  188.24 141.05 270 bottom
CV354  -  [C_0402]  190.02 140.13 90 bottom
CV355  -  [C_0402]  201.39 157.07 90 bottom
CV356  -  [C_0402]  199.61 157.99 270 bottom
CV368  -  [C_0402]  184.18 158.28 90 top
CV369  -  [C_0402]  185.26 158.15 90 bottom
CV370  -  [C_0402]  192.24 158.34 90 top
CV371  -  [C_0402]  183.29 158.28 90 top
CV372  -  [C_0402]  171.42 158.22 90 bottom
CV373  -  [C_0402]  174.59 158.54 90 top
CV374  -  [C_0402]  169.07 158.22 90 bottom
CV375  -  [C_0402]  168.18 158.22 90 bottom
CV376  -  [C_0402]  193.96 158.15 90 bottom
CV377  -  [C_0402]  192.5 158.15 90 bottom
CV378  -  [C_0402]  170.53 158.22 90 bottom
CV379  -  [C_0402]  189.58 158.28 90 top
CV380  -  [C_0402]  172.81 158.54 90 bottom
CV381  -  [C_0402]  191.61 158.15 90 bottom
CV382  -  [C_0402]  190.21 158.15 90 bottom
CV383  -  [C_0402]  187.8 158.28 90 top
CV384  -  [C_0402]  218.52 134.67 0 bottom
CV385  -  [C_0402]  219.03 132.2 0 top
CV386  -  [C_0402]  218.52 130.23 0 bottom
CV387  -  [C_0402]  159.05 154.99 180 top
CV388  -  [C_0402]  170.78 140.2 90 bottom
CV389  -  [C_0402]  200.96 159.95 180 top
CV390  -  [C_0402]  200.04 158.17 0 top
CV391  -  [C_0402]  218.77 108.95 0 top
CV392  -  [C_0402]  218.33 114.48 0 top
CV393  -  [C_0402]  158.13 153.21 0 top
CV394  -  [C_0402]  176.18 159.31 270 bottom
CV395  -  [C_0402]  177.96 158.4 90 bottom
CV396  -  [C_0402]  176.18 159.31 270 top
CV397  -  [C_0402]  168.11 141.11 270 bottom
CV398  -  [C_0402]  177.96 158.4 90 top
CV399  -  [C_0402]  169 141.11 270 top
CV400  -  [C_0402]  159.03 148.78 270 top
CV401  -  [C_0402]  182.4 158.28 90 top
CX1  -  [C_0402]  224.77 176.01 180 top
CX2  -  [C_0402]  219.1 170.7 270 bottom
CX3  -  [C_0805]  220.44 170.59 270 bottom
CX4  -  [C_0402]  228.03 178.54 90 top
CX5  -  [C_0603]  232.57 177.98 90 top
CX7  -  [C_0805]  224.16 174.31 0 top
CX8  -  [C_0805]  222.15 173.57 270 bottom
CX9  -  [C_0402]  218.16 169.55 180 top
CX10  -  [C_0402]  213.57 163.12 0 bottom
CX11  -  [C_0402]  224.82 173.5 270 bottom
CX12  -  [C_0402]  20.02 103.68 0 bottom
CX13  -  [C_0402]  20.02 102.8 0 bottom
CX14  -  [C_0402]  19.13 106.35 0 bottom
CX15  -  [C_0402]  19.13 105.46 0 bottom
CX16  -  [C_0402]  18.18 101.02 0 bottom
CX17  -  [C_0402]  18.18 100.13 0 bottom
CX18  -  [C_0402]  19.07 98.35 0 bottom
CX19  -  [C_0402]  19.07 97.46 0 bottom
CX20  -  [C_0402]  15.09 113.48 180 bottom
CX21  -  [C_0402]  14.13 109.41 270 bottom
CX22  -  [C_0603]  15.21 109.4 270 bottom
CX23  -  [C_0402]  15.01 103.67 90 bottom
CX24  -  [C_0402]  15.01 102.81 270 bottom
CX25  -  [C_0402]  14.13 106.34 90 bottom
CX26  -  [C_0402]  14.13 105.47 270 bottom
CX27  -  [C_0402]  13.11 101.07 90 bottom
CX28  -  [C_0402]  13.11 100.2 270 bottom
CX29  -  [C_0402]  14 98.4 90 bottom
CX30  -  [C_0402]  14 97.54 270 bottom
CX31  -  [C_0402]  199.3 172.67 180 bottom
CX32  -  [C_0402]  199.33 169.62 180 top
CX33  -  [C_0402]  199.3 171.8 180 bottom
CX34  -  [C_0402]  203.99 167.32 270 top
CX35  -  [C_0603]  198.33 169.73 180 bottom
CX36  -  [C_0805]  206.82 166.87 0 top
CX37  -  [C_0402]  204.24 177.47 90 top
CX38  -  [C_0402]  196.66 171.2 0 top
CX39  -  [C_0402]  196.66 170.31 0 top
CX40  -  [C_0402]  204.64 165.03 180 top
CX41  -  [C_0402]  205.77 167.32 270 top
CX42  -  [C_0402]  198.52 172.39 0 top
CX43  -  [C_0402]  198.52 173.28 0 top
CX44  -  [C_0402]  198.49 174.17 0 top
CX45  -  [C_0603]  204.56 163.95 180 top
CX46  -  [C_0402]  198.52 171.5 0 top
CX47  -  [C_0402]  199.74 163.69 180 top
CX48  -  [C_0805]  198.9 165.32 90 top
DA8  -  [BAT54C-7-F_SOT23-3]  50.38 29.49 0 top
DA10  -  [AZ5125-02SPR7G_SOT23-3]  29.43 18.25 180 top
DA12  -  [AZ5125-02SPR7G_SOT23-3]  15.74 24.77 270 top
DC1  -  [BAT54CW_SOT323-3]  111.53 12.78 0 bottom
DE1  -  [L03ESDL5V0CG3-2_SOT-523-3]  173 42.19 90 top
DH1  -  [RB751V-40_SOD323-2]  144.25 119.63 270 bottom
DI1  -  [IP4292CZ10-TBR_XSON10_2P5X1]  16.69 61.92 90 bottom
DI2  -  [L30ESDL5V0C3-2_SOT23-3]  17.09 59.04 90 bottom
DI4  -  [IP4292CZ10-TBR_XSON10_2P5X1]  17.51 48.77 90 bottom
DI5  -  [L30ESDL5V0C3-2_SOT23-3]  16.58 46.28 90 bottom
DI7  -  [L30ESDL5V0C3-2_SOT23-3]  15.18 30.61 90 bottom
DX1  -  [RB751V-40_SOD323-2]  215.87 168.93 270 top
FD1  -  [FIDUCIAL_C40M80]  231.74 162.82 180 bottom
FD2  -  [FIDUCIAL_C40M80]  32.22 12.96 180 bottom
FD3  -  [FIDUCIAL_C40M80]  33.68 14.99 0 top
FD4  -  [FIDUCIAL_C40M80]  231.68 162.82 0 top
FE1  -  [F_1812L075-24DR]  40.61 110.18 270 top
FX1  -  [F_1206L150PR]  14.31 110.99 0 bottom
H1  -  [H_2P8]  63.63 26.48 0 top
H2  -  [H_2P8]  95.75 16.9 0 top
H4  -  [H_5P0N]  19.2 73.9 0 top
H5  -  [H_2P8]  21.9 17.9 0 top
H6  -  [H_3P3]  204.1 96.4 0 top
H7  -  [H_3P3]  153.3 146.51 0 top
H8  -  [H_2P8]  225.2 83.4 0 top
H9  -  [H_2P8]  231.9 170.1 0 top
H10  -  [H_3P3]  26.92 121.11 0 top
H11  -  [H_2P8]  182.2 187.2 0 top
H12  -  [H_2P8]  32.2 111.4 0 top
H16  -  [H_2P8]  127.6 156.8 0 top
H17  -  [H_2P8]  225.85 9.4 0 top
H18  -  [H_5P0X3P0N]  19.2 40.1 0 top
H19  -  [H_3P5]  230.3 96.45 0 top
H20  -  [H_3P5]  230.3 122.75 0 top
H31  -  [H_3P7]  80.8 131.06 0 top
H32  -  [H_3P7]  141.2 105.66 0 top
H33  -  [H_3P7]  141.2 131.06 0 top
H34  -  [H_3P7]  80.8 105.66 0 top
H35  -  [H_3P0]  225.2 168.6 0 top
J9  -  [JUMP_43X39]  185.84 88.51 180 bottom
J510  -  [JUMP_43X79]  197.62 21.72 180 top
J511  -  [JUMP_43X79]  197.62 17.78 180 top
J513  -  [JUMP_43X79]  139.79 30.76 270 top
JBTB  -  [ACES_50100-0127N-001_12P]  227.19 107.63 270 bottom
JBTB1  -  [E-T_1133-Q12C-01R_12P]  227.54 111.63 270 bottom
JDB  -  [JESS_UCNR2210M008-0_8P]  210.6 38.93 270 top
JDIMM1  -  [LCN_DAN06-K4406-0102_204P]  41.8 73.41 0 bottom
JDIMM2  -  [LCN_DAN06-K4406-0102_204P]  120.35 73.45 0 bottom
JFAN  -  [ACES_85204-0300N_3P]  48.69 110.62 0 bottom
JHDD  -  [SANTA_194301-1_22P]  229.05 28.64 270 bottom
JHDMI  -  [LOTES_ABA-HDM-022-K01_19P]  7.78 101.15 270 bottom
JHP  -  [SINGA_2SJ3080-000111F_6P-T]  11.43 9.98 270 bottom
JKB  -  [HB_A823020-SBHR21_30P]  228.6 161.83 270 top
JKBBL  -  [HB_A090420-SAHR21_4P]  40.99 114.33 90 top
JLAN  -  [SANTA_130456-311_8P]  14.25 81.21 90 bottom
JLVDS  -  [STARC_107K40-000001-G2_40P]  212.51 175.71 0 bottom
JMINI  -  [CONCR_525B01BE17A_52P]  92.3 152.67 0 bottom
JP3  -  [JUMP_43X39]  45.16 88.95 0 bottom
JP7  -  [JUMP_43X79]  220.21 117.84 0 bottom
JP8  -  [JUMP_43X39]  182.13 93.58 0 bottom
JP9  -  [JUMP_43X39]  214.01 153.27 0 bottom
JP12  -  [JUMP_43X39]  114.53 14.09 180 bottom
JP13  -  [JUMP_43X79]  222.55 52.95 270 top
JPWR  -  [HB_A090420-SAHR21_4P]  26.79 96.4 180 top
JREAD  -  [T-SOL_143-2300302602_22P_RV]  191.47 25.63 180 bottom
JRTC  -  [LOTES_AAA-BAT-054-K01_2P]  110.9 22.34 180 bottom
JSPK  -  [E-T_3703-Q04N-11R_4P]  67.86 33.92 90 top
JTP  -  [PS_HPF10052-06M000R_6P]  58.3 112.14 0 top
JUSB1  -  [ACON_TARA4-9K1311_9P]  12.37 69.1 90 bottom
JUSB2  -  [ACON_TARA4-9K1311_9P]  12.37 51.5 90 bottom
JUSB3  -  [ACON_UARBG-4K1926_4P]  9.97 33.9 90 bottom
JXDP1  -  [SAMTE_BSH-030-01-L-D-A_60P]  73.2 95.44 180 bottom
L1  -  [MURAT_LQM2MPN2R2NG0L_2P]  119.54 139.79 270 bottom
L2  -  [MURAT_LQM2MPN2R2NG0L_2P]  121.02 143.99 0 bottom
L3  -  [MURAT_LQM2MPN2R2NG0L_2P]  123.88 141.2 0 bottom
L4  -  [MURAT_LQM2MPN2R2NG0L_2P]  121.76 142.25 270 bottom
L5  -  [MURAT_LQM2MPN2R2NG0L_2P]  117.31 139.79 270 bottom
LA1  -  [MURAT_BLM15BB221SN1D_2P]  44.55 23.26 0 top
LA3  -  [R_0603]  62.13 32.75 0 top
LA4  -  [R_0603]  62.13 33.96 0 top
LA5  -  [R_0603]  61.18 35.74 0 top
LA6  -  [R_0603]  61.18 36.95 0 top
LA7  -  [KC_FBMA-L10-160808-800LMT_2P]  20.79 25.72 0 top
LA8  -  [KC_FBMA-L10-160808-800LMT_2P]  29.51 21.67 90 top
LA9  -  [KC_FBMA-L10-160808-800LMT_2P]  27.97 21.67 90 top
LA10  -  [KC_FBMA-L10-160808-800LMT_2P]  20.79 24.2 0 top
LE1  -  [KC_FBMA-L11-160808-800LMT_2P]  199.62 37.71 0 top
LE2  -  [KC_FBMA-L11-160808-800LMT_2P]  194.21 57.51 270 top
LED1  -  [LED_12-21C-T3D-CM2P1B18X-2C_3P]  23.46 11.94 0 top
LED2  -  [LED_12-21C-T3D-CM2P1B18X-2C_3P]  32.42 11.88 0 top
LED3  -  [LED_HT-210UD5-BP5_3P]  38.53 11.88 0 top
LED4  -  [LED_12-21C-T3D-CM2P1B18X-2C_3P]  50.43 11.89 0 top
LI1  -  [MURAT_DLW21SN670HQ2L_4P]  21.26 61.5 180 bottom
LI2  -  [KC_WCM-2012HS-900T_4P]  23.42 60.33 180 bottom
LI3  -  [MURAT_DLW21SN670HQ2L_4P]  21.26 63.41 180 bottom
LI4  -  [MURAT_DLW21SN670HQ2L_4P]  22.34 48.17 180 bottom
LI5  -  [KC_WCM-2012HS-900T_4P]  22.85 46.62 180 bottom
LI6  -  [MURAT_DLW21SN670HQ2L_4P]  22.34 49.94 180 bottom
LI7  -  [KC_WCM-2012HS-900T_4P]  20.88 31 180 bottom
LI10  -  [KC_WCM-2012HS-900T_4P]  206.38 39.14 90 top
LR2  -  [KC_WCM-2012HS-900T_4P]  173.6 28.72 180 bottom
LV12  -  [R_0402]  162.59 114.65 270 top
LV13  -  [R_0402]  162.59 117.15 270 top
LV14  -  [R_0402]  160.55 108.2 270 bottom
LV15  -  [R_0402]  160.55 105.85 270 bottom
LV16  -  [R_0402]  159.54 107.28 90 bottom
LV17  -  [CHENG_MBK1608121YZF_2P]  153.38 113.29 90 top
LV18  -  [CHENG_MBK1608121YZF_2P]  156.77 116.76 0 bottom
LV19  -  [R_0402]  169.05 98.74 0 bottom
LV20  -  [R_0402]  184.1 101.52 0 bottom
LV21  -  [KC_FBMA-L11-160808-800LMT_2P]  203.72 151 180 top
LV22  -  [R_0402]  191.75 96.76 180 bottom
LV23  -  [KC_FBMA-L11-160808-800LMT_2P]  194.21 94.93 90 bottom
LV25  -  [R_0402]  180.95 115.11 180 top
LV26  -  [R_0402]  182.28 116.69 180 top
LX1  -  [KC_FBMA-L11-201209-221LMA30_2P]  220.37 171.83 90 bottom
LX2  -  [KC_WCM-2012HS-900T_4P]  17.83 103.64 180 bottom
LX3  -  [KC_WCM-2012HS-900T_4P]  16.94 106.31 180 bottom
LX4  -  [KC_WCM-2012HS-900T_4P]  15.93 101.04 180 bottom
LX5  -  [KC_WCM-2012HS-900T_4P]  16.82 98.31 180 bottom
LX6  -  [KC_WCM-2012HS-900T_4P]  219.02 166.72 90 top
LX7  -  [KC_FBMA-L11-201209-221LMA30_2P]  205.96 164.9 270 top
LX8  -  [KC_FBMA-L11-201209-221LMA30_2P]  197.62 168.09 0 bottom
LX9  -  [CYNTE_PG031B-4R7MS_2P]  200.48 166.23 0 top
ME1  -  [SHORTPADS]  115.4 40.96 180 bottom
NOREF  -  []  21.9 17.9 0 top
NOREF#2  -  []  225.2 168.6 0 top
NOREF#3  -  []  127.6 156.81 0 top
NOREF#4  -  []  108.36 -18.49 0 top
NOREF#5  -  []  26.92 121.11 0 top
NOREF#6  -  []  141.2 105.66 0 top
NOREF#7  -  []  89.63 51.2 0 top
NOREF#8  -  []  153.3 146.51 0 top
NOREF#9  -  []  80.8 105.67 0 top
NOREF#10  -  []  204.1 96.41 0 top
NOREF#11  -  []  225.85 9.4 0 top
NOREF#12  -  []  108.61 90.3 0 top
NOREF#13  -  []  95.75 16.9 0 top
NOREF#14  -  []  230.3 122.75 0 top
NOREF#15  -  []  74.7 86.55 0 top
NOREF#16  -  []  63.63 26.48 0 top
NOREF#17  -  []  225.85 74.01 0 top
NOREF#18  -  []  47.46 51.46 0 top
NOREF#19  -  []  230.3 96.45 0 top
NOREF#20  -  []  80.8 131.07 0 top
NOREF#21  -  []  182.2 187.2 0 top
NOREF#22  -  []  225.2 83.41 0 top
NOREF#23  -  []  119.35 41.34 0 top
NOREF#24  -  []  141.2 131.06 0 top
NOREF#25  -  []  32.2 111.4 0 top
NOREF#26  -  []  231.9 170.1 0 top
NOREF#27  -  []  225.2 5.4 0 top
NOREF#28  -  []  179.33 49.2 180 bottom
NOREF#29  -  []  97.08 33.16 180 bottom
NOREF#30  -  []  149.38 40.45 180 bottom
NOREF#31  -  []  97.25 88.27 180 bottom
PBATT  -  [SUYIN_200028MR009G502ZL_9P]  157.07 190.7 0 bottom
PC1  -  [C_0402]  139.79 181.9 90 bottom
PC2  -  [C_0402]  140.68 181.9 90 bottom
PC3  -  [C_0402]  138.71 170.5 270 top
PC4  -  [C_0402]  137.82 170.5 270 top
PC5  -  [C_0402]  127.16 174.17 90 top
PC7  -  [C_0402]  158.07 183.06 0 bottom
PC8  -  [C_0402]  158.07 184.2 0 bottom
PC13  -  [C_0402]  130.85 182.81 180 top
PC14  -  [C_0402]  132.11 166.5 270 top
PC15  -  [C_0402]  127.54 165.58 90 top
PC16  -  [C_0402]  127.47 169.33 90 top
PC100  -  [C_0603]  203.74 29.23 0 top
PC101  -  [C_MP6VLPS220MC4R2]  206.09 8.57 270 bottom
PC102  -  [C_0402]  203.14 18.23 0 top
PC103  -  [C_0603]  210.53 18.61 0 bottom
PC104  -  [C_0402]  206.86 16.53 270 top
PC105  -  [C_0603]  209.15 19.51 90 bottom
PC106  -  [C_0603]  211.26 20.47 90 bottom
PC107  -  [C_MP6VLPS220MC4R2]  205.96 31.95 90 bottom
PC108  -  [C_0402]  204.07 21.38 180 bottom
PC109  -  [C_0603]  203.99 20.23 180 top
PC110  -  [C_0402]  207.47 24.84 270 top
PC111  -  [C_0603]  210.47 23.05 0 bottom
PC112  -  [C_0805]  216.13 19.94 180 bottom
PC113  -  [C_0402]  216.32 22.99 180 bottom
PC114  -  [C_0402]  216.32 18.61 180 bottom
PC115  -  [C_0805]  216.13 21.66 180 bottom
PC200  -  [C_0603]  154.91 23.69 0 bottom
PC201  -  [C_0402]  163.8 16.96 270 bottom
PC202  -  [C_0402]  162 26.34 0 bottom
PC203  -  [C_0402]  162 28.12 0 bottom
PC204  -  [C_0603]  159.67 22.04 90 bottom
PC205  -  [C_0805]  154.91 29.15 270 bottom
PC206  -  [C_0805]  159.86 18.37 270 bottom
PC207  -  [C_0402]  156.42 13.2 0 bottom
PC208  -  [C_0402]  162.91 16.96 270 bottom
PC209  -  [C_0603]  160.88 23.43 270 bottom
PC210  -  [C_0402]  159.67 30.23 90 bottom
PC211  -  [C_0805]  156.88 30.61 0 bottom
PC212  -  [C_0805]  161.57 18.37 270 bottom
PC213  -  [C_MP6VU330MC6]  146.34 24.45 0 bottom
PC300  -  [C_0402]  148.17 152.13 0 bottom
PC301  -  [C_0603]  139.23 152.51 90 bottom
PC302  -  [C_0603]  148.43 160.06 180 bottom
PC303  -  [C_0402]  143.42 159.29 90 bottom
PC304  -  [C_0402]  142.53 159.29 90 bottom
PC305  -  [C_0805]  141.32 157.17 270 bottom
PC306  -  [C_0805]  139.61 157.17 270 bottom
PC307  -  [C_0402]  147.74 155.73 90 bottom
PC308  -  [C_0805]  141.7 144.36 90 top
PC309  -  [C_0805]  143.41 144.36 90 top
PC310  -  [C_0805]  146.84 144.36 90 top
PC311  -  [C_0805]  145.13 144.36 90 top
PC312  -  [C_0603]  147.04 157.65 0 bottom
PC313  -  [C_0603]  144.5 159.49 0 bottom
PC400  -  [C_0805]  110.3 28.31 0 bottom
PC401  -  [C_0402]  105.32 18.02 0 bottom
PC402  -  [C_0805]  110.57 26.88 270 bottom
PC403  -  [C_0402]  107.46 18.37 180 top
PC404  -  [C_0402]  109.98 18.04 180 top
PC405  -  [C_0805]  105.17 15.15 90 bottom
PC501  -  [C_0402]  117.62 140.83 180 bottom
PC502  -  [C_0402]  114.34 147.05 270 bottom
PC503  -  [C_0603]  82.9 137.4 90 bottom
PC504  -  [C_0402]  86.95 138.36 0 top
PC505  -  [C_0603]  90.14 133.67 0 bottom
PC506  -  [C_0402]  88.74 138.3 270 top
PC507  -  [C_0402]  89.94 137.39 90 top
PC508  -  [C_0603]  89.69 144.71 270 bottom
PC509  -  [C_0402]  90.26 141.86 270 top
PC510  -  [C_0402]  93.89 141.09 180 bottom
PC511  -  [C_0402]  93.89 141.97 180 bottom
PC512  -  [C_0402]  86.95 137.47 0 top
PC513  -  [C_0402]  92.66 136.39 0 bottom
PC514  -  [C_0402]  91.79 134.67 90 bottom
PC515  -  [C_EEEFZ1E101P]  129.63 145.62 270 bottom
PC516  -  [C_EEEFZ1E101P]  136.74 145.17 270 bottom
PC517  -  [C_0805]  117.47 145.24 90 top
PC518  -  [C_0805]  117.47 145.24 90 bottom
PC519  -  [C_0402]  115.23 146.14 90 bottom
PC520  -  [C_0402]  107.22 144.82 90 top
PC521  -  [C_0402]  116.12 146.14 90 bottom
PC522  -  [C_0402]  85.46 141.9 180 bottom
PC523  -  [C_0402]  83.67 137.61 180 top
PC600  -  [C_0805]  217.87 100.26 0 top
PC601  -  [C_0402]  216.61 94.67 0 bottom
PC602  -  [C_0805]  217.87 98.22 0 top
PC603  -  [C_0402]  220.06 95.38 270 top
PC604  -  [C_0402]  222.16 90.03 180 bottom
PC605  -  [C_0805]  217.14 91.97 90 bottom
PC701  -  [C_0603]  143.03 171.18 270 bottom
PC702  -  [C_0402]  143.81 168.64 180 bottom
PC703  -  [C_0805]  157.55 168.28 0 top
PC704  -  [C_0805]  157.55 166.5 0 top
PC705  -  [C_0402]  158 170.87 0 top
PC706  -  [C_0603]  157.83 169.79 0 top
PC707  -  [C_0603]  167.41 169.66 0 bottom
PC708  -  [C_0402]  166.4 169.47 90 bottom
PC709  -  [C_0603]  164.68 174.55 180 top
PC710  -  [C_0603]  163.92 169.09 180 top
PC711  -  [C_0402]  172.25 170.11 180 top
PC712  -  [C_0805]  146.63 181.73 0 top
PC713  -  [C_0805]  146.63 183.44 0 top
PC714  -  [C_0805]  145.93 177.98 0 top
PC715  -  [C_0402]  154.77 178.61 0 top
PC716  -  [C_0805]  146.63 185.15 0 top
PC717  -  [C_0402]  167.75 167.95 180 top
PC718  -  [C_0805]  145.93 176.26 0 top
PC719  -  [C_0402]  169.64 176.07 270 top
PC720  -  [C_0402]  195.61 53.72 270 bottom
PC721  -  [C_0603]  162.53 170.36 0 top
PC722  -  [C_0402]  167.73 177.15 0 top
PC723  -  [C_0402]  171.99 179.12 180 top
PC724  -  [C_EEEFZ1E101P]  157.1 166.04 0 bottom
